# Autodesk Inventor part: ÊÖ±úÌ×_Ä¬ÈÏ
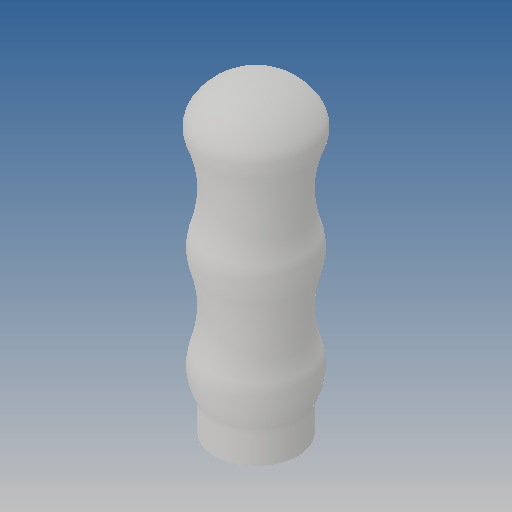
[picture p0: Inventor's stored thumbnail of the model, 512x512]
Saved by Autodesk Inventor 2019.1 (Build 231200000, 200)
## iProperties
Created: 2012-10
Part Number: ÊÖ±úÌ×_Ä¬ÈÏ
Material: Ogólny
Document SubType Name: Modeling
Designer: CADENGINEERING4
Density: 1 g/cm^3
Appearance: Domyślna
Author: CADENGINEERING4
Revision Number: ÈÎºÎ
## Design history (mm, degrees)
feature "NONE"
node "Bryła1"
